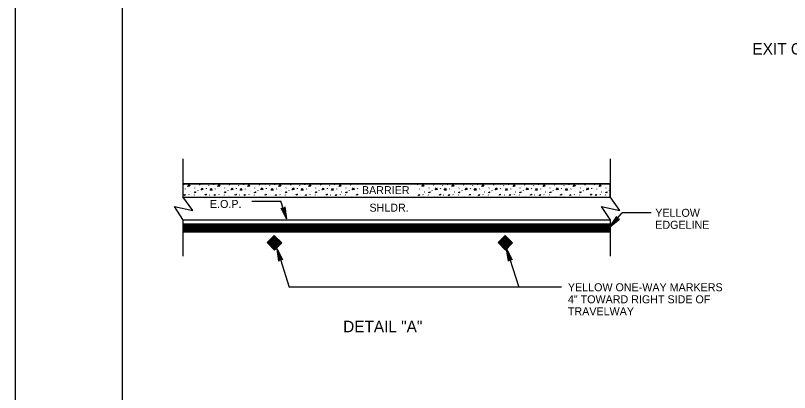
# Model space of a CAD drawing. Extents: x 639362 to 641108, y 298458 to 299646.
# Drawn here: x 639362.3 to 639652.3, y 299349.9 to 299491.1 of the extents above; entities that cross this region are included whole.
import ezdxf

# ---------------------------------------------------------------- set-up
doc = ezdxf.new("R2010")
doc.units = 0
for name, color, linetype in [('1', 7, 'Continuous'), ('2', 7, 'Continuous'), ('PLT-BNDY', 7, 'Continuous')]:
    doc.layers.add(name, color=color, linetype=linetype)

msp = doc.modelspace()

# ---------------------------------------------------------------- linework, layer by layer
at = {"layer": '1'}
msp.add_line((639402.31, 299630.63), (639402.31, 299066.63), dxfattribs=at)
at = {"layer": '2'}
for p, q in [((639425.06, 299437.38), (639425.06, 299423.17)), ((639585.06, 299437.38), (639585.06, 299423.17)), ((639425.06, 299428), (639585.06, 299428)), ((639425.22, 299427.76), (639425.28, 299427.67)), ((639431.19, 299427.61), (639431.25, 299427.52)), ((639433.71, 299427.84), (639433.77, 299427.74)), ((639434.57, 299427.41), (639434.64, 299427.32)), ((639436.45, 299427.76), (639436.51, 299427.67)), ((639442.41, 299427.61), (639442.47, 299427.52)), ((639444.93, 299427.84), (639444.99, 299427.74)), ((639445.8, 299427.41), (639445.86, 299427.32)), ((639447.67, 299427.76), (639447.73, 299427.67)), ((639453.63, 299427.61), (639453.7, 299427.52)), ((639456.15, 299427.84), (639456.22, 299427.74)), ((639457.46, 299427.41), (639457.52, 299427.32)), ((639459.33, 299427.76), (639459.39, 299427.67)), ((639465.29, 299427.61), (639465.35, 299427.52)), ((639467.81, 299427.84), (639467.87, 299427.74)), ((639468.68, 299427.41), (639468.74, 299427.32)), ((639470.55, 299427.76), (639470.62, 299427.67)), ((639476.52, 299427.61), (639476.58, 299427.52)), ((639479.04, 299427.84), (639479.1, 299427.74)), ((639479.99, 299427.41), (639480.05, 299427.32)), ((639481.86, 299427.76), (639481.93, 299427.67)), ((639487.83, 299427.61), (639487.89, 299427.52)), ((639490.35, 299427.84), (639490.41, 299427.74)), ((639512.95, 299427.76), (639513.01, 299427.67)), ((639518.91, 299427.61), (639518.97, 299427.52)), ((639521.43, 299427.84), (639521.49, 299427.74)), ((639522.3, 299427.41), (639522.36, 299427.32)), ((639524.17, 299427.76), (639524.24, 299427.67)), ((639530.14, 299427.61), (639530.2, 299427.52)), ((639532.66, 299427.84), (639532.72, 299427.74)), ((639533.53, 299427.41), (639533.59, 299427.32)), ((639535.4, 299427.76), (639535.46, 299427.67)), ((639541.36, 299427.61), (639541.42, 299427.52)), ((639543.88, 299427.84), (639543.94, 299427.74)), ((639545.18, 299427.41), (639545.24, 299427.32)), ((639547.05, 299427.76), (639547.12, 299427.67)), ((639553.02, 299427.61), (639553.08, 299427.52)), ((639555.54, 299427.84), (639555.6, 299427.74)), ((639556.41, 299427.41), (639556.47, 299427.32)), ((639558.28, 299427.76), (639558.34, 299427.67)), ((639564.24, 299427.61), (639564.3, 299427.52)), ((639566.76, 299427.84), (639566.82, 299427.74)), ((639567.72, 299427.41), (639567.78, 299427.32)), ((639569.59, 299427.76), (639569.65, 299427.67)), ((639575.55, 299427.61), (639575.61, 299427.52)), ((639578.07, 299427.84), (639578.13, 299427.74)), ((639579.26, 299427.76), (639579.32, 299427.67)), ((639426, 299426.01), (639426.06, 299426.15)), ((639427.23, 299424.03), (639427.3, 299423.94)), ((639427.84, 299425.07), (639427.9, 299424.98)), ((639429.22, 299423.86), (639429.28, 299423.77)), ((639429.5, 299426.35), (639429.55, 299426.49)), ((639430.61, 299425.54), (639430.67, 299425.45)), ((639433.83, 299426.2), (639433.89, 299426.33)), ((639434.92, 299423.95), (639434.98, 299423.86)), ((639437.22, 299426.01), (639437.28, 299426.15)), ((639438.46, 299424.03), (639438.52, 299423.94)), ((639439.06, 299425.07), (639439.12, 299424.98)), ((639440.44, 299423.86), (639440.51, 299423.77)), ((639440.72, 299426.35), (639440.78, 299426.49)), ((639441.83, 299425.54), (639441.89, 299425.45)), ((639445.05, 299426.2), (639445.11, 299426.33)), ((639446.14, 299423.95), (639446.21, 299423.86)), ((639448.45, 299426.01), (639448.5, 299426.15)), ((639449.68, 299424.03), (639449.75, 299423.94)), ((639450.29, 299425.07), (639450.35, 299424.98)), ((639451.67, 299423.86), (639451.73, 299423.77)), ((639451.95, 299426.35), (639452, 299426.49)), ((639453.06, 299425.54), (639453.12, 299425.45)), ((639456.28, 299426.2), (639456.33, 299426.33)), ((639457.8, 299423.95), (639457.86, 299423.86)), ((639460.1, 299426.01), (639460.16, 299426.15)), ((639461.34, 299424.03), (639461.4, 299423.94)), ((639461.94, 299425.07), (639462.01, 299424.98)), ((639463.33, 299423.86), (639463.39, 299423.77)), ((639463.6, 299426.35), (639463.66, 299426.49)), ((639464.71, 299425.54), (639464.77, 299425.45)), ((639467.93, 299426.2), (639467.99, 299426.33)), ((639469.02, 299423.95), (639469.09, 299423.86)), ((639471.33, 299426.01), (639471.39, 299426.15)), ((639472.56, 299424.03), (639472.63, 299423.94)), ((639473.17, 299425.07), (639473.23, 299424.98)), ((639474.55, 299423.86), (639474.61, 299423.77)), ((639474.83, 299426.35), (639474.88, 299426.49)), ((639475.94, 299425.54), (639476, 299425.45)), ((639479.16, 299426.2), (639479.22, 299426.33)), ((639480.34, 299423.95), (639480.4, 299423.86)), ((639482.64, 299426.01), (639482.7, 299426.15)), ((639483.88, 299424.03), (639483.94, 299423.94)), ((639484.48, 299425.07), (639484.54, 299424.98)), ((639485.86, 299423.86), (639485.92, 299423.77)), ((639486.14, 299426.35), (639486.2, 299426.49)), ((639487.25, 299425.54), (639487.31, 299425.45)), ((639490.47, 299426.2), (639490.53, 299426.33)), ((639513.72, 299426.01), (639513.78, 299426.15)), ((639514.96, 299424.03), (639515.02, 299423.94)), ((639515.56, 299425.07), (639515.63, 299424.98)), ((639516.95, 299423.86), (639517.01, 299423.77)), ((639517.22, 299426.35), (639517.28, 299426.49)), ((639518.33, 299425.54), (639518.39, 299425.45)), ((639521.55, 299426.2), (639521.61, 299426.33)), ((639522.64, 299423.95), (639522.71, 299423.86)), ((639524.95, 299426.01), (639525.01, 299426.15)), ((639526.18, 299424.03), (639526.25, 299423.94)), ((639526.79, 299425.07), (639526.85, 299424.98)), ((639528.17, 299423.86), (639528.23, 299423.77)), ((639528.45, 299426.35), (639528.5, 299426.49)), ((639529.56, 299425.54), (639529.62, 299425.45)), ((639532.78, 299426.2), (639532.84, 299426.33)), ((639533.87, 299423.95), (639533.93, 299423.86)), ((639536.17, 299426.01), (639536.23, 299426.15)), ((639537.41, 299424.03), (639537.47, 299423.94)), ((639538.01, 299425.07), (639538.08, 299424.98)), ((639539.4, 299423.86), (639539.46, 299423.77)), ((639539.67, 299426.35), (639539.73, 299426.49)), ((639540.78, 299425.54), (639540.84, 299425.45)), ((639544, 299426.2), (639544.06, 299426.33)), ((639545.53, 299423.95), (639545.59, 299423.86)), ((639547.83, 299426.01), (639547.89, 299426.15)), ((639549.07, 299424.03), (639549.13, 299423.94)), ((639549.67, 299425.07), (639549.73, 299424.98)), ((639551.05, 299423.86), (639551.11, 299423.77)), ((639551.33, 299426.35), (639551.39, 299426.49)), ((639552.44, 299425.54), (639552.5, 299425.45)), ((639555.66, 299426.2), (639555.72, 299426.33)), ((639556.75, 299423.95), (639556.81, 299423.86)), ((639559.06, 299426.01), (639559.11, 299426.15)), ((639560.29, 299424.03), (639560.35, 299423.94)), ((639560.9, 299425.07), (639560.96, 299424.98)), ((639562.28, 299423.86), (639562.34, 299423.77)), ((639562.55, 299426.35), (639562.61, 299426.49)), ((639563.66, 299425.54), (639563.72, 299425.45)), ((639566.89, 299426.2), (639566.94, 299426.33)), ((639568.06, 299423.95), (639568.12, 299423.86)), ((639570.37, 299426.01), (639570.42, 299426.15)), ((639571.6, 299424.03), (639571.66, 299423.94)), ((639572.21, 299425.07), (639572.27, 299424.98)), ((639573.59, 299423.86), (639573.65, 299423.77)), ((639573.87, 299426.35), (639573.92, 299426.49)), ((639574.97, 299425.54), (639575.04, 299425.45)), ((639578.2, 299426.2), (639578.25, 299426.33)), ((639580.04, 299426.01), (639580.09, 299426.15)), ((639581.27, 299424.03), (639581.33, 299423.94)), ((639581.88, 299425.07), (639581.94, 299424.98)), ((639583.26, 299423.86), (639583.32, 299423.77)), ((639583.54, 299426.35), (639583.59, 299426.49)), ((639584.64, 299425.54), (639584.71, 299425.45)), ((639428.7, 299418.07), (639425.06, 299423.17)), ((639425.06, 299423), (639585.06, 299423)), ((639431.44, 299423.06), (639431.49, 299423.19)), ((639442.66, 299423.06), (639442.72, 299423.19)), ((639450.9, 299421.49), (639461.77, 299421.49)), ((639453.89, 299423.06), (639453.94, 299423.19)), ((639463.89, 299414.84), (639461.77, 299421.49)), ((639465.54, 299423.06), (639465.6, 299423.19)), ((639476.77, 299423.06), (639476.83, 299423.19)), ((639488.08, 299423.06), (639488.14, 299423.19)), ((639519.16, 299423.06), (639519.22, 299423.19)), ((639530.39, 299423.06), (639530.45, 299423.19)), ((639541.61, 299423.06), (639541.67, 299423.19)), ((639553.27, 299423.06), (639553.33, 299423.19)), ((639564.5, 299423.06), (639564.55, 299423.19)), ((639575.81, 299423.06), (639575.86, 299423.19)), ((639588.71, 299418.07), (639585.06, 299423.17)), ((639425.06, 299414.7), (639421.88, 299419.47)), ((639421.88, 299419.47), (639428.7, 299418.07)), ((639585.06, 299414.7), (639581.89, 299419.47)), ((639581.89, 299419.47), (639588.71, 299418.07)), ((639584.99, 299411.91), (639589.61, 299417.14)), ((639600.47, 299417.14), (639589.61, 299417.14)), ((639425.06, 299414.7), (639425.06, 299400.87)), ((639425.06, 299414.5), (639585.06, 299414.5)), ((639425.06, 299413), (639585.06, 299413)), ((639425.06, 299413), (639585.06, 299413)), ((639425.06, 299413), (639585.06, 299413)), ((639425.06, 299412.7), (639585.06, 299412.7)), ((639425.06, 299412.4), (639585.06, 299412.4)), ((639585.06, 299414.7), (639585.06, 299400.87)), ((639425.06, 299412.1), (639585.06, 299412.1)), ((639425.06, 299411.8), (639585.06, 299411.8)), ((639425.06, 299411.5), (639585.06, 299411.5)), ((639425.06, 299411.2), (639585.06, 299411.2)), ((639425.06, 299410.9), (639585.06, 299410.9)), ((639425.06, 299410.6), (639585.06, 299410.6)), ((639425.06, 299410.3), (639585.06, 299410.3)), ((639425.06, 299410), (639585.06, 299410)), ((639456.57, 299406.04), (639459.22, 299408.69)), ((639456.91, 299406.09), (639459.17, 299408.35)), ((639457.29, 299406.1), (639459.17, 299407.98)), ((639457.66, 299406.09), (639459.17, 299407.6)), ((639458.04, 299406.1), (639459.17, 299407.22)), ((639458.42, 299406.1), (639459.17, 299406.85)), ((639458.79, 299406.1), (639459.17, 299406.47)), ((639459.17, 299408.35), (639461.71, 299405.81)), ((639459.17, 299407.98), (639461.33, 299405.82)), ((639459.17, 299407.6), (639460.96, 299405.81)), ((639459.17, 299407.22), (639460.58, 299405.82)), ((639459.17, 299406.85), (639460.2, 299405.81)), ((639459.17, 299406.47), (639459.83, 299405.81)), ((639459.22, 299408.69), (639462.04, 299405.87)), ((639543.08, 299406.04), (639545.73, 299408.69)), ((639543.42, 299406.09), (639545.68, 299408.35)), ((639543.8, 299406.1), (639545.68, 299407.98)), ((639544.17, 299406.09), (639545.68, 299407.6)), ((639544.55, 299406.1), (639545.68, 299407.22)), ((639544.92, 299406.1), (639545.68, 299406.85)), ((639545.3, 299406.1), (639545.68, 299406.47)), ((639545.68, 299408.35), (639548.21, 299405.81)), ((639545.68, 299407.98), (639547.84, 299405.82)), ((639545.68, 299407.6), (639547.46, 299405.81)), ((639545.68, 299407.22), (639547.09, 299405.82)), ((639545.68, 299406.85), (639546.71, 299405.81)), ((639545.68, 299406.47), (639546.33, 299405.81)), ((639545.73, 299408.69), (639548.54, 299405.87)), ((639459.39, 299403.22), (639456.57, 299406.04)), ((639459.45, 299403.55), (639456.91, 299406.09)), ((639459.45, 299403.93), (639457.29, 299406.1)), ((639459.45, 299404.31), (639457.66, 299406.09)), ((639459.45, 299404.69), (639458.04, 299406.1)), ((639459.45, 299405.06), (639458.42, 299406.1)), ((639459.45, 299405.44), (639458.79, 299406.1)), ((639459.16, 299406.1), (639459.45, 299405.81)), ((639462.04, 299405.87), (639459.39, 299403.22)), ((639461.33, 299405.82), (639459.45, 299403.93)), ((639460.58, 299405.82), (639459.45, 299404.69)), ((639461.71, 299405.81), (639459.45, 299403.55)), ((639460.96, 299405.81), (639459.45, 299404.31)), ((639460.2, 299405.81), (639459.45, 299405.06)), ((639459.83, 299405.81), (639459.45, 299405.44)), ((639460.29, 299403.62), (639464.87, 299389.27)), ((639545.89, 299403.22), (639543.08, 299406.04)), ((639545.96, 299403.55), (639543.42, 299406.09)), ((639545.96, 299403.93), (639543.8, 299406.1)), ((639545.96, 299404.31), (639544.17, 299406.09)), ((639545.96, 299404.69), (639544.55, 299406.1)), ((639545.96, 299405.06), (639544.92, 299406.1)), ((639545.96, 299405.44), (639545.3, 299406.1)), ((639545.67, 299406.1), (639545.96, 299405.81)), ((639548.54, 299405.87), (639545.89, 299403.22)), ((639547.84, 299405.82), (639545.96, 299403.93)), ((639547.09, 299405.82), (639545.96, 299404.69)), ((639548.21, 299405.81), (639545.96, 299403.55)), ((639547.46, 299405.81), (639545.96, 299404.31)), ((639546.71, 299405.81), (639545.96, 299405.06)), ((639546.33, 299405.81), (639545.96, 299405.44)), ((639546.3, 299403.62), (639550.88, 299389.27)), ((639566.79, 299389.27), (639464.87, 299389.27))]:
    msp.add_line(p, q, dxfattribs=at)
msp.add_lwpolyline([(639425.06, 299423), (639585.06, 299423), (639585.06, 299428), (639425.06, 299428)], close=True, dxfattribs=at)
for points in [[(639426.87, 299427.03), (639427.26, 299427.78), (639427.57, 299427.09), (639426.88, 299427.03)], [(639438.09, 299427.03), (639438.49, 299427.78), (639438.8, 299427.09), (639438.11, 299427.03)], [(639449.31, 299427.03), (639449.71, 299427.78), (639450.02, 299427.09), (639449.33, 299427.03)], [(639460.97, 299427.03), (639461.37, 299427.78), (639461.68, 299427.09), (639460.99, 299427.03)], [(639472.2, 299427.03), (639472.6, 299427.78), (639472.9, 299427.09), (639472.21, 299427.03)], [(639483.51, 299427.03), (639483.91, 299427.78), (639484.22, 299427.09), (639483.52, 299427.03)], [(639514.59, 299427.03), (639514.99, 299427.78), (639515.3, 299427.09), (639514.61, 299427.03)], [(639525.82, 299427.03), (639526.22, 299427.78), (639526.52, 299427.09), (639525.83, 299427.03)], [(639537.04, 299427.03), (639537.44, 299427.78), (639537.75, 299427.09), (639537.06, 299427.03)], [(639548.7, 299427.03), (639549.1, 299427.78), (639549.41, 299427.09), (639548.71, 299427.03)], [(639559.92, 299427.03), (639560.32, 299427.78), (639560.63, 299427.09), (639559.94, 299427.03)], [(639571.23, 299427.03), (639571.63, 299427.78), (639571.94, 299427.09), (639571.25, 299427.03)], [(639580.9, 299427.03), (639581.3, 299427.78), (639581.61, 299427.09), (639580.92, 299427.03)], [(639425.55, 299423.63), (639425.73, 299424), (639426.03, 299423.78), (639425.55, 299423.63)], [(639429.39, 299424.69), (639429.57, 299425.05), (639429.86, 299424.83), (639429.39, 299424.69)], [(639431.83, 299425.81), (639432.23, 299426.56), (639432.55, 299425.86), (639431.85, 299425.81)], [(639433.39, 299423.81), (639433.56, 299424.19), (639433.86, 299423.97), (639433.39, 299423.81)], [(639435.23, 299425.61), (639435.63, 299426.37), (639435.94, 299425.68), (639435.24, 299425.61)], [(639436.78, 299423.63), (639436.95, 299424), (639437.25, 299423.78), (639436.78, 299423.63)], [(639440.62, 299424.69), (639440.8, 299425.05), (639441.09, 299424.83), (639440.62, 299424.69)], [(639443.06, 299425.81), (639443.46, 299426.56), (639443.77, 299425.86), (639443.07, 299425.81)], [(639444.61, 299423.81), (639444.79, 299424.19), (639445.09, 299423.97), (639444.61, 299423.81)], [(639446.45, 299425.61), (639446.85, 299426.37), (639447.16, 299425.68), (639446.46, 299425.61)], [(639448, 299423.63), (639448.18, 299424), (639448.48, 299423.78), (639448, 299423.63)], [(639451.84, 299424.69), (639452.02, 299425.05), (639452.31, 299424.83), (639451.84, 299424.69)], [(639454.28, 299425.81), (639454.68, 299426.56), (639455, 299425.86), (639454.3, 299425.81)], [(639455.84, 299423.81), (639456.01, 299424.19), (639456.31, 299423.97), (639455.84, 299423.81)], [(639458.11, 299425.61), (639458.51, 299426.37), (639458.82, 299425.68), (639458.12, 299425.61)], [(639459.66, 299423.63), (639459.83, 299424), (639460.13, 299423.78), (639459.66, 299423.63)], [(639463.5, 299424.69), (639463.68, 299425.05), (639463.97, 299424.83), (639463.5, 299424.69)], [(639465.94, 299425.81), (639466.34, 299426.56), (639466.65, 299425.86), (639465.95, 299425.81)], [(639467.5, 299423.81), (639467.67, 299424.19), (639467.97, 299423.97), (639467.5, 299423.81)], [(639469.33, 299425.61), (639469.73, 299426.37), (639470.04, 299425.68), (639469.34, 299425.61)], [(639470.89, 299423.63), (639471.06, 299424), (639471.36, 299423.78), (639470.89, 299423.63)], [(639474.72, 299424.69), (639474.9, 299425.05), (639475.19, 299424.83), (639474.72, 299424.69)], [(639477.16, 299425.81), (639477.56, 299426.56), (639477.88, 299425.86), (639477.18, 299425.81)], [(639478.72, 299423.81), (639478.9, 299424.19), (639479.19, 299423.97), (639478.72, 299423.81)], [(639480.64, 299425.61), (639481.04, 299426.37), (639481.35, 299425.68), (639480.66, 299425.61)], [(639482.2, 299423.63), (639482.37, 299424), (639482.67, 299423.78), (639482.2, 299423.63)], [(639486.03, 299424.69), (639486.21, 299425.05), (639486.51, 299424.83), (639486.03, 299424.69)], [(639488.47, 299425.81), (639488.87, 299426.56), (639489.19, 299425.86), (639488.49, 299425.81)], [(639490.03, 299423.81), (639490.21, 299424.19), (639490.5, 299423.97), (639490.03, 299423.81)], [(639513.28, 299423.63), (639513.45, 299424), (639513.75, 299423.78), (639513.28, 299423.63)], [(639517.12, 299424.69), (639517.3, 299425.05), (639517.59, 299424.83), (639517.12, 299424.69)], [(639519.56, 299425.81), (639519.96, 299426.56), (639520.27, 299425.86), (639519.57, 299425.81)], [(639521.12, 299423.81), (639521.29, 299424.19), (639521.59, 299423.97), (639521.12, 299423.81)], [(639522.95, 299425.61), (639523.35, 299426.37), (639523.66, 299425.68), (639522.96, 299425.61)], [(639524.51, 299423.63), (639524.68, 299424), (639524.98, 299423.78), (639524.51, 299423.63)], [(639528.34, 299424.69), (639528.52, 299425.05), (639528.81, 299424.83), (639528.34, 299424.69)], [(639530.78, 299425.81), (639531.18, 299426.56), (639531.5, 299425.86), (639530.8, 299425.81)], [(639532.34, 299423.81), (639532.52, 299424.19), (639532.81, 299423.97), (639532.34, 299423.81)], [(639534.18, 299425.61), (639534.58, 299426.37), (639534.89, 299425.68), (639534.19, 299425.61)], [(639535.73, 299423.63), (639535.9, 299424), (639536.2, 299423.78), (639535.73, 299423.63)], [(639539.57, 299424.69), (639539.75, 299425.05), (639540.04, 299424.83), (639539.57, 299424.69)], [(639542.01, 299425.81), (639542.41, 299426.56), (639542.72, 299425.86), (639542.02, 299425.81)], [(639543.57, 299423.81), (639543.74, 299424.19), (639544.04, 299423.97), (639543.57, 299423.81)], [(639545.83, 299425.61), (639546.23, 299426.37), (639546.54, 299425.68), (639545.85, 299425.61)], [(639547.39, 299423.63), (639547.56, 299424), (639547.86, 299423.78), (639547.39, 299423.63)], [(639551.22, 299424.69), (639551.4, 299425.05), (639551.7, 299424.83), (639551.22, 299424.69)], [(639553.66, 299425.81), (639554.06, 299426.56), (639554.38, 299425.86), (639553.68, 299425.81)], [(639555.22, 299423.81), (639555.4, 299424.19), (639555.69, 299423.97), (639555.22, 299423.81)], [(639557.06, 299425.61), (639557.46, 299426.37), (639557.77, 299425.68), (639557.07, 299425.61)], [(639558.61, 299423.63), (639558.79, 299424), (639559.08, 299423.78), (639558.61, 299423.63)], [(639562.45, 299424.69), (639562.63, 299425.05), (639562.92, 299424.83), (639562.45, 299424.69)], [(639564.89, 299425.81), (639565.29, 299426.56), (639565.6, 299425.86), (639564.91, 299425.81)], [(639566.45, 299423.81), (639566.62, 299424.19), (639566.92, 299423.97), (639566.45, 299423.81)], [(639568.37, 299425.61), (639568.77, 299426.37), (639569.08, 299425.68), (639568.38, 299425.61)], [(639569.92, 299423.63), (639570.1, 299424), (639570.39, 299423.78), (639569.92, 299423.63)], [(639573.76, 299424.69), (639573.94, 299425.05), (639574.23, 299424.83), (639573.76, 299424.69)], [(639576.2, 299425.81), (639576.6, 299426.56), (639576.91, 299425.86), (639576.22, 299425.81)], [(639577.76, 299423.81), (639577.93, 299424.19), (639578.23, 299423.97), (639577.76, 299423.81)], [(639579.59, 299423.63), (639579.77, 299424), (639580.07, 299423.78), (639579.59, 299423.63)], [(639583.43, 299424.69), (639583.61, 299425.05), (639583.9, 299424.83), (639583.43, 299424.69)], [(639463.07, 299419.12), (639462.82, 299418.87), (639463.89, 299414.84), (639463.07, 299419.12), (639463.18, 299419.38), (639463.89, 299414.84), (639462.41, 299418.72), (639462.07, 299418.78), (639463.89, 299414.84), (639461.8, 299418.93), (639462.07, 299418.78)], [(639587.46, 299415.49), (639587.59, 299415.16), (639584.99, 299411.91), (639587.46, 299415.49), (639587.47, 299415.78), (639584.99, 299411.91), (639587.91, 299414.87), (639588.24, 299414.78), (639584.99, 299411.91), (639588.55, 299414.81), (639588.24, 299414.78)], [(639461.12, 299399.35), (639461.36, 299399.6), (639460.29, 299403.62), (639461.12, 299399.35), (639461, 299399.08), (639460.29, 299403.62), (639461.78, 299399.74), (639462.12, 299399.69), (639460.29, 299403.62), (639462.39, 299399.53), (639462.12, 299399.69)], [(639547.12, 299399.35), (639547.37, 299399.6), (639546.3, 299403.62), (639547.12, 299399.35), (639547.01, 299399.08), (639546.3, 299403.62), (639547.78, 299399.74), (639548.12, 299399.69), (639546.3, 299403.62), (639548.39, 299399.53), (639548.12, 299399.69)]]:
    msp.add_lwpolyline(points, dxfattribs=at)
at = {"layer": 'PLT-BNDY'}
msp.add_lwpolyline([(639362.31, 299645.63), (640203.31, 299645.63), (640203.31, 299051.63), (639362.31, 299051.63)], close=True, dxfattribs=at)

# ---------------------------------------------------------------- texts
at = {"layer": '2'}
for s, height, p in [('EXIT GORE AREA', 4.3, (639638.38, 299476.41)), ('BARRIER', 3, (639492.1, 299424.15)), ('E.O.P.', 3, (639435.16, 299418.97)), ('SHLDR.', 3, (639494.91, 299417.59)), ('YELLOW ', 3, (639601.97, 299415.66)), ('EDGELINE', 3, (639601.97, 299411.16)), ('YELLOW ONE-WAY MARKERS', 3, (639569.25, 299387.77)), ('4" TOWARD RIGHT SIDE OF ', 3, (639569.25, 299383.27)), ('TRAVELWAY', 3, (639569.25, 299378.77)), ('DETAIL "A"', 4.3, (639485.06, 299372.43))]:
    msp.add_text(s, height=height, dxfattribs=at).set_placement(p)

doc.saveas('drawing.dxf')
